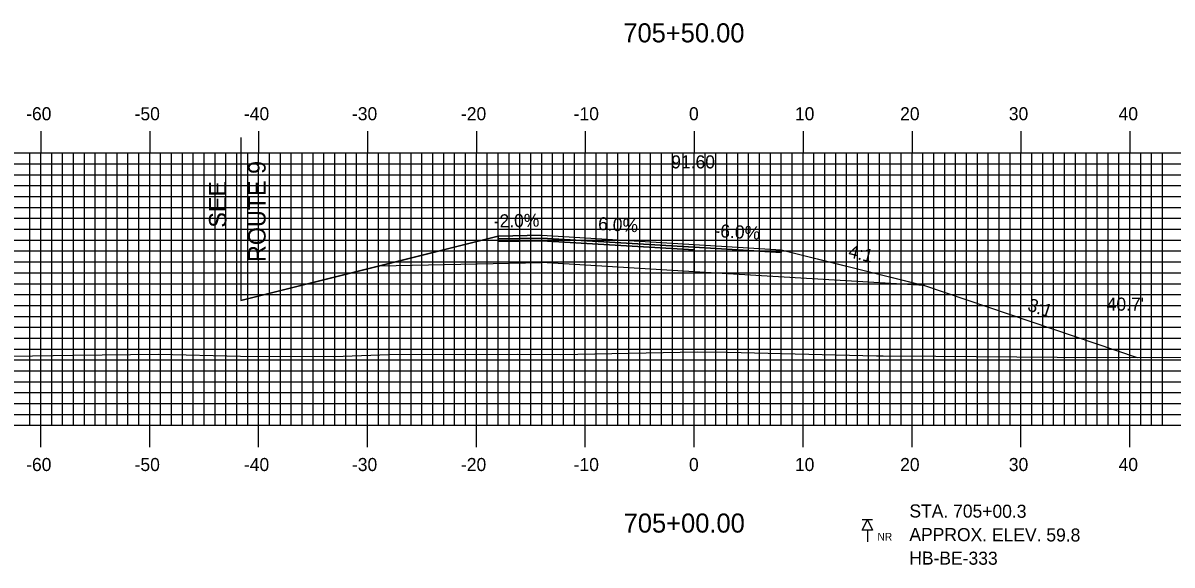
# Model space of a CAD drawing. Extents: x 853723 to 854066, y 364366 to 364586.
# Drawn here: x 853827.1 to 853932.6, y 364421 to 364470.7 of the extents above; entities that cross this region are included whole.
import ezdxf

# ---------------------------------------------------------------- set-up
doc = ezdxf.new("R2010")
doc.units = 0
for name, color, linetype in [('ANNOTATION', 7, 'Continuous'), ('BORING - NO REFUSAL', 7, 'Continuous'), ('D_Roadway_Centerline', 7, 'Continuous'), ('D_Roadway_Centerline_Text', 7, 'Continuous'), ('D_Roadway_Edge_Shoulder', 7, 'Continuous'), ('D_Roadway_Edge_TW', 7, 'Continuous'), ('D_Roadway_Pavement', 7, 'Continuous'), ('D_Roadway_SlopeLines', 7, 'Continuous'), ('D_Roadway_SubGrade', 7, 'Continuous'), ('D_Text_Standard', 7, 'Continuous'), ('H_V ANNOTATION', 7, 'Continuous'), ('MAJOR', 7, 'Continuous'), ('MINOR', 7, 'Continuous'), ('S_Roadway_Centerline', 7, 'Continuous')]:
    doc.layers.add(name, color=color, linetype=linetype)

msp = doc.modelspace()

# ---------------------------------------------------------------- linework, layer by layer
at = {"layer": 'BORING - NO REFUSAL'}
for p, q in [((853905.1, 364425.12), (853904.14, 364425.12)), ((853904.62, 364424.16), (853904.62, 364423.1))]:
    msp.add_line(p, q, dxfattribs=at)
msp.add_lwpolyline([(853904.62, 364425.12), (853905.1, 364424.16), (853904.14, 364424.16)], close=True, dxfattribs=at)
at = {"layer": 'D_Roadway_Centerline'}
msp.add_lwpolyline([(853847.1, 364445.24), (853859.85, 364448.43), (853870.72, 364451.15), (853874.72, 364451.23), (853888.72, 364450.39), (853896.72, 364449.91), (853908.72, 364446.91), (853909.88, 364446.62), (853929.39, 364440.02)], dxfattribs=at)
at = {"layer": 'D_Roadway_Edge_Shoulder'}
for points in [[(853874.72, 364451.23), (853870.72, 364451.15), (853870.72, 364450.9), (853874.72, 364450.98)], [(853888.72, 364450.39), (853896.72, 364449.91), (853896.72, 364449.66), (853888.72, 364450.14)]]:
    msp.add_lwpolyline(points, close=True, dxfattribs=at)
at = {"layer": 'D_Roadway_Edge_TW'}
msp.add_lwpolyline([(853874.72, 364451.23), (853888.72, 364450.39), (853888.72, 364450.14), (853874.72, 364450.98)], close=True, dxfattribs=at)
at = {"layer": 'D_Roadway_Pavement'}
for points in [[(853874.72, 364450.98), (853870.72, 364450.9), (853870.72, 364450.65), (853874.72, 364450.73)], [(853874.72, 364450.98), (853888.72, 364450.14), (853888.72, 364449.89), (853874.72, 364450.73)]]:
    msp.add_lwpolyline(points, close=True, dxfattribs=at)
msp.add_lwpolyline([(853888.72, 364450.14), (853888.72, 364449.89)], dxfattribs=at)
msp.add_lwpolyline([(853888.72, 364450.14), (853888.72, 364449.89)], dxfattribs=at)
at = {"layer": 'D_Roadway_SlopeLines'}
for points in [[(853870.72, 364451.15), (853847.1, 364445.24)], [(853896.72, 364449.91), (853909.88, 364446.62), (853929.39, 364440.02)]]:
    msp.add_lwpolyline(points, dxfattribs=at)
at = {"layer": 'D_Roadway_SubGrade'}
msp.add_line((853847.1, 364460.2), (853847.1, 364445.24), dxfattribs=at)
for points in [[(853874.72, 364450.73), (853870.72, 364450.65), (853870.72, 364450.9), (853870.72, 364451.15), (853859.85, 364448.43), (853874.72, 364448.73)], [(853874.72, 364450.73), (853888.72, 364449.89), (853888.72, 364447.89), (853874.72, 364448.73)], [(853888.72, 364449.89), (853888.72, 364450.14), (853896.72, 364449.66), (853896.72, 364449.91), (853909.88, 364446.62), (853888.72, 364447.89)]]:
    msp.add_lwpolyline(points, close=True, dxfattribs=at)
at = {"layer": 'MAJOR'}
for p, q in [((853828.72, 364460.79), (853828.72, 364458.79)), ((853838.72, 364460.79), (853838.72, 364458.79)), ((853848.72, 364460.79), (853848.72, 364458.79)), ((853858.72, 364460.79), (853858.72, 364458.79)), ((853868.72, 364460.79), (853868.72, 364458.79)), ((853878.72, 364460.79), (853878.72, 364458.79)), ((853888.72, 364460.79), (853888.72, 364458.79)), ((853898.72, 364460.79), (853898.72, 364458.79)), ((853908.72, 364460.79), (853908.72, 364458.79)), ((853918.72, 364460.79), (853918.72, 364458.79)), ((853928.72, 364460.79), (853928.72, 364458.79)), ((853748.72, 364458.79), (854028.72, 364458.79)), ((853748.72, 364458.79), (854028.72, 364458.79)), ((853828.72, 364433.79), (853828.72, 364458.79)), ((853838.72, 364433.79), (853838.72, 364458.79)), ((853848.72, 364433.79), (853848.72, 364458.79)), ((853858.72, 364433.79), (853858.72, 364458.79)), ((853868.72, 364433.79), (853868.72, 364458.79)), ((853878.72, 364433.79), (853878.72, 364458.79)), ((853888.72, 364433.79), (853888.72, 364458.79)), ((853898.72, 364433.79), (853898.72, 364458.79)), ((853908.72, 364433.79), (853908.72, 364458.79)), ((853918.72, 364433.79), (853918.72, 364458.79)), ((853928.72, 364433.79), (853928.72, 364458.79)), ((853748.72, 364453.79), (854028.72, 364453.79)), ((853748.72, 364448.79), (854028.72, 364448.79)), ((853748.72, 364443.79), (854028.72, 364443.79)), ((853748.72, 364438.79), (854028.72, 364438.79)), ((853748.72, 364433.79), (854028.72, 364433.79)), ((853748.72, 364433.79), (854028.72, 364433.79)), ((853828.72, 364431.78), (853828.72, 364433.79)), ((853838.72, 364431.78), (853838.72, 364433.79)), ((853848.72, 364431.78), (853848.72, 364433.79)), ((853858.72, 364431.78), (853858.72, 364433.79)), ((853868.72, 364431.78), (853868.72, 364433.79)), ((853878.72, 364431.78), (853878.72, 364433.79)), ((853888.72, 364431.78), (853888.72, 364433.79)), ((853898.72, 364431.78), (853898.72, 364433.79)), ((853908.72, 364431.78), (853908.72, 364433.79)), ((853918.72, 364431.78), (853918.72, 364433.79)), ((853928.72, 364431.78), (853928.72, 364433.79))]:
    msp.add_line(p, q, dxfattribs=at)
at = {"layer": 'MINOR'}
for p, q in [((853827.72, 364433.79), (853827.72, 364458.79)), ((853829.72, 364433.79), (853829.72, 364458.79)), ((853830.72, 364433.79), (853830.72, 364458.79)), ((853831.72, 364433.79), (853831.72, 364458.79)), ((853832.72, 364433.79), (853832.72, 364458.79)), ((853833.72, 364433.79), (853833.72, 364458.79)), ((853834.72, 364433.79), (853834.72, 364458.79)), ((853835.72, 364433.79), (853835.72, 364458.79)), ((853836.72, 364433.79), (853836.72, 364458.79)), ((853837.72, 364433.79), (853837.72, 364458.79)), ((853839.72, 364433.79), (853839.72, 364458.79)), ((853840.72, 364433.79), (853840.72, 364458.79)), ((853841.72, 364433.79), (853841.72, 364458.79)), ((853842.72, 364433.79), (853842.72, 364458.79)), ((853843.72, 364433.79), (853843.72, 364458.79)), ((853844.72, 364433.79), (853844.72, 364458.79)), ((853845.72, 364433.79), (853845.72, 364458.79)), ((853846.72, 364433.79), (853846.72, 364458.79)), ((853847.72, 364433.79), (853847.72, 364458.79)), ((853849.72, 364433.79), (853849.72, 364458.79)), ((853850.72, 364433.79), (853850.72, 364458.79)), ((853851.72, 364433.79), (853851.72, 364458.79)), ((853852.72, 364433.79), (853852.72, 364458.79)), ((853853.72, 364433.79), (853853.72, 364458.79)), ((853854.72, 364433.79), (853854.72, 364458.79)), ((853855.72, 364433.79), (853855.72, 364458.79)), ((853856.72, 364433.79), (853856.72, 364458.79)), ((853857.72, 364433.79), (853857.72, 364458.79)), ((853859.72, 364433.79), (853859.72, 364458.79)), ((853860.72, 364433.79), (853860.72, 364458.79)), ((853861.72, 364433.79), (853861.72, 364458.79)), ((853862.72, 364433.79), (853862.72, 364458.79)), ((853863.72, 364433.79), (853863.72, 364458.79)), ((853864.72, 364433.79), (853864.72, 364458.79)), ((853865.72, 364433.79), (853865.72, 364458.79)), ((853866.72, 364433.79), (853866.72, 364458.79)), ((853867.72, 364433.79), (853867.72, 364458.79)), ((853869.72, 364433.79), (853869.72, 364458.79)), ((853870.72, 364433.79), (853870.72, 364458.79)), ((853871.72, 364433.79), (853871.72, 364458.79)), ((853872.72, 364433.79), (853872.72, 364458.79)), ((853873.72, 364433.79), (853873.72, 364458.79)), ((853874.72, 364433.79), (853874.72, 364458.79)), ((853875.72, 364433.79), (853875.72, 364458.79)), ((853876.72, 364433.79), (853876.72, 364458.79)), ((853877.72, 364433.79), (853877.72, 364458.79)), ((853879.72, 364433.79), (853879.72, 364458.79)), ((853880.72, 364433.79), (853880.72, 364458.79)), ((853881.72, 364433.79), (853881.72, 364458.79)), ((853882.72, 364433.79), (853882.72, 364458.79)), ((853883.72, 364433.79), (853883.72, 364458.79)), ((853884.72, 364433.79), (853884.72, 364458.79)), ((853885.72, 364433.79), (853885.72, 364458.79)), ((853886.72, 364433.79), (853886.72, 364458.79)), ((853887.72, 364433.79), (853887.72, 364458.79)), ((853889.72, 364433.79), (853889.72, 364458.79)), ((853890.72, 364433.79), (853890.72, 364458.79)), ((853891.72, 364433.79), (853891.72, 364458.79)), ((853892.72, 364433.79), (853892.72, 364458.79)), ((853893.72, 364433.79), (853893.72, 364458.79)), ((853894.72, 364433.79), (853894.72, 364458.79)), ((853895.72, 364433.79), (853895.72, 364458.79)), ((853896.72, 364433.79), (853896.72, 364458.79)), ((853897.72, 364433.79), (853897.72, 364458.79)), ((853899.72, 364433.79), (853899.72, 364458.79)), ((853900.72, 364433.79), (853900.72, 364458.79)), ((853901.72, 364433.79), (853901.72, 364458.79)), ((853902.72, 364433.79), (853902.72, 364458.79)), ((853903.72, 364433.79), (853903.72, 364458.79)), ((853904.72, 364433.79), (853904.72, 364458.79)), ((853905.72, 364433.79), (853905.72, 364458.79)), ((853906.72, 364433.79), (853906.72, 364458.79)), ((853907.72, 364433.79), (853907.72, 364458.79)), ((853909.72, 364433.79), (853909.72, 364458.79)), ((853910.72, 364433.79), (853910.72, 364458.79)), ((853911.72, 364433.79), (853911.72, 364458.79)), ((853912.72, 364433.79), (853912.72, 364458.79)), ((853913.72, 364433.79), (853913.72, 364458.79)), ((853914.72, 364433.79), (853914.72, 364458.79)), ((853915.72, 364433.79), (853915.72, 364458.79)), ((853916.72, 364433.79), (853916.72, 364458.79)), ((853917.72, 364433.79), (853917.72, 364458.79)), ((853919.72, 364433.79), (853919.72, 364458.79)), ((853920.72, 364433.79), (853920.72, 364458.79)), ((853921.72, 364433.79), (853921.72, 364458.79)), ((853922.72, 364433.79), (853922.72, 364458.79)), ((853923.72, 364433.79), (853923.72, 364458.79)), ((853924.72, 364433.79), (853924.72, 364458.79)), ((853925.72, 364433.79), (853925.72, 364458.79)), ((853926.72, 364433.79), (853926.72, 364458.79)), ((853927.72, 364433.79), (853927.72, 364458.79)), ((853929.72, 364433.79), (853929.72, 364458.79)), ((853930.72, 364433.79), (853930.72, 364458.79)), ((853931.72, 364433.79), (853931.72, 364458.79)), ((853748.72, 364457.79), (854028.72, 364457.79)), ((853748.72, 364456.79), (854028.72, 364456.79)), ((853748.72, 364455.79), (854028.72, 364455.79)), ((853748.72, 364454.79), (854028.72, 364454.79)), ((853748.72, 364452.79), (854028.72, 364452.79)), ((853748.72, 364451.79), (854028.72, 364451.79)), ((853748.72, 364450.79), (854028.72, 364450.79)), ((853748.72, 364449.79), (854028.72, 364449.79)), ((853748.72, 364447.79), (854028.72, 364447.79)), ((853748.72, 364446.79), (854028.72, 364446.79)), ((853748.72, 364445.79), (854028.72, 364445.79)), ((853748.72, 364444.79), (854028.72, 364444.79)), ((853748.72, 364442.79), (854028.72, 364442.79)), ((853748.72, 364441.79), (854028.72, 364441.79)), ((853748.72, 364440.79), (854028.72, 364440.79)), ((853748.72, 364439.79), (854028.72, 364439.79)), ((853748.72, 364437.79), (854028.72, 364437.79)), ((853748.72, 364436.79), (854028.72, 364436.79)), ((853748.72, 364435.79), (854028.72, 364435.79)), ((853748.72, 364434.79), (854028.72, 364434.79))]:
    msp.add_line(p, q, dxfattribs=at)
at = {"layer": 'S_Roadway_Centerline'}
msp.add_lwpolyline([(853822.25, 364440.08), (853831.74, 364440.22), (853839.54, 364440.31), (853847.04, 364440.14), (853855.62, 364440.09), (853860.7, 364440.28), (853872.46, 364440.33), (853876.48, 364440.28), (853888.99, 364440.54), (853891.79, 364440.49), (853905.45, 364440.16), (853906.08, 364440.18), (853910.9, 364440.13), (853922.05, 364440.03), (853935.35, 364440.01)], dxfattribs=at)

# ---------------------------------------------------------------- texts
at = {"layer": 'ANNOTATION'}
for s, height, rotation, p in [('ROUTE 9', 1.6, 90, (853849.36, 364448.78)), ('SEE', 1.6, 90, (853845.76, 364451.93)), ('-2.0%', 1.2, 1.1458, (853870.32, 364451.94)), ('6.0%', 1.2, 356.5664, (853879.87, 364451.72)), ('-6.0%', 1.2, 356.5664, (853890.55, 364451.08)), ('4:1', 1.2, 345.9638, (853902.8, 364449.25)), ('3:1', 1.2, 341.3106, (853919.24, 364444.36))]:
    msp.add_text(s, height=height, rotation=rotation, dxfattribs=at).set_placement(p)
at = {"layer": 'BORING - NO REFUSAL'}
for s, p in [('STA. 705+00.3', (853908.48, 364425.33)), ('APPROX. ELEV. 59.8', (853908.48, 364423.17)), ('HB-BE-333', (853908.47, 364421.01))]:
    msp.add_text(s, height=1.2, rotation=359.8142, dxfattribs=at).set_placement(p)
msp.add_text('NR', height=0.7, dxfattribs=at).set_placement((853905.55, 364423.21))
at = {"layer": 'D_Roadway_Centerline_Text'}
msp.add_text('91.60', height=1.2, dxfattribs=at).set_placement((853886.61, 364457.37))
at = {"layer": 'D_Text_Standard'}
msp.add_text("40.7'", height=1.2, dxfattribs=at).set_placement((853926.6, 364444.31))
at = {"layer": 'H_V ANNOTATION'}
for s, height, p in [('705+50.00', 1.75, (853882.21, 364468.94)), ('-60', 1.2, (853827.37, 364461.79)), ('-50', 1.2, (853837.33, 364461.79)), ('-40', 1.2, (853847.37, 364461.79)), ('-30', 1.2, (853857.29, 364461.79)), ('-20', 1.2, (853867.3, 364461.79)), ('-10', 1.2, (853877.65, 364461.79)), ('0', 1.2, (853888.24, 364461.79)), ('10', 1.2, (853897.97, 364461.79)), ('20', 1.2, (853907.63, 364461.79)), ('30', 1.2, (853917.61, 364461.79)), ('40', 1.2, (853927.69, 364461.79)), ('-60', 1.2, (853827.37, 364429.59)), ('-50', 1.2, (853837.33, 364429.59)), ('-40', 1.2, (853847.37, 364429.59)), ('-30', 1.2, (853857.29, 364429.59)), ('-20', 1.2, (853867.3, 364429.59)), ('-10', 1.2, (853877.65, 364429.59)), ('0', 1.2, (853888.24, 364429.59)), ('10', 1.2, (853897.97, 364429.59)), ('20', 1.2, (853907.63, 364429.59)), ('30', 1.2, (853917.61, 364429.59)), ('40', 1.2, (853927.69, 364429.59)), ('705+00.00', 1.75, (853882.24, 364423.94))]:
    msp.add_text(s, height=height, dxfattribs=at).set_placement(p)

doc.saveas('drawing.dxf')
